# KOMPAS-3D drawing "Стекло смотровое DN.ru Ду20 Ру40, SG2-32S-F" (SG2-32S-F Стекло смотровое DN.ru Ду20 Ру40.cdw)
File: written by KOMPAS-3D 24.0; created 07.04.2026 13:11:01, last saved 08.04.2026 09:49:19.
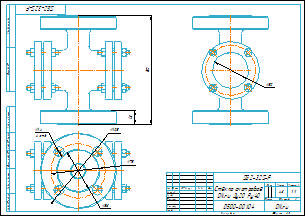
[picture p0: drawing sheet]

Document properties: Автор: Main; Форматы листов документа: A3; Полное имя файла: SG2-32S-F Стекло смотровое DN.ru Ду20 Ру40.m3d; Масса: 4.8; Наименование: Стекло смотровое DN.ru Ду20 Ру40; Количество листов документа: 1; Примечание: D500-00104

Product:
- Body: Тело 1  | qty 1
    Масса: 3.869459
- Part/product: Стекло смотровое DN.ru Ду20 Ру40  | designation SG2-32S-F
    Масса: 4.8
    Раздел спецификации: Прочие изделия
    Примечание: D500-00104

Views: Вид 1, Снизу, Проекционный вид 2
Referenced files in D:\DN.ru Аутсерс\Стекло смотровое DN.ru\Стекло смотровое DN.ru SG2-34G-F тип В ГОСТ 21836-2021 Ду100 Ру16, углеродистая сталь, фланцевое\: SG2-34G-F тип В Стекло смотровое DN.ru Ду100 Ру16.m3d, SG2-34G-F тип ВСтекло смотровое DN.ru Ду100 Ру16.cdw
Referenced files in D:\DN.ru Аутсерс\Стекло смотровое DN.ru\SG2-32S-F Стекло смотровое DN.ru Ду20 Ру40\: SG2-32S-F Стекло смотровое DN.ru Ду20 Ру40.m3d
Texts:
  SG2-32S-F
  Стекло смотровое
  DN.ru Ду20 Ру40
  Стекло смотровое DN.ru Ду20 Ру40
  SG2-32S-F Стекло смотровое DN.ru Ду20 Ру40
Dimensions and other numbers on the sheet: 0; 3; 2; 4; 150; 18; 14; 4 отв.; 105; 75; 58; 1:1; 1; 4,8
